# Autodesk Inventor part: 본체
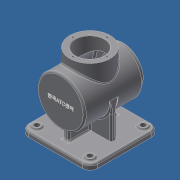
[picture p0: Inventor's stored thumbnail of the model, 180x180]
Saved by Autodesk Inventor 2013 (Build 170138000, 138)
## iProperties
Created: 2015-07
Part Number: 본체
Material: 일반
Document SubType Name: Modeling
Designer: Administrator
Density: 1 g/cm^3
Mass: 471.466 g
Surface Area: 1268.22 cm^2
Volume: 471.466 cm^3
Author: Administrator
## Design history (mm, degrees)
sketch "스케치1"
  geometry: L1 (-65, 65)-(65, 65); L2 (65, 65)-(65, -65); L3 (65, -65)-(-65, -65); L4 (-65, -65)-(-65, 65); 3 further points
  constraints: 8 end point, 2 midpoint, 2 parallel, 1 horizontal, 1 horizontal alignment, 1 perpendicular, 1 vertical alignment
  dimensions: "d0" = 130 distance of L1.start L1.end; "d2" = 130 distance of L1.end L2.end
extrude "돌출1" new body sketch "스케치1" distance "d3" = 10; taper "d4" = 0 deg
node "작업 평면1"
node "작업 평면2"
node "작업 평면3"
sketch "스케치8"
  geometry: L1 (0, 0)-(130, 0) reference; L2 (130, 0)-(130, -10) reference; L3 (0, -10)-(130, -10) reference; L4 (0, 0)-(0, -10) reference; C1 r 45 at (65, 68); 2 further points
  constraints: 1 centre point, 1 midpoint, 1 vertical alignment
  dimensions: "d32" = 90 diameter of C1; "d34" = 78 distance from line of L3 C1.centre
extrude "돌출7" join sketch "스케치8" distance "d35" = 110; taper "d36" = 0 deg
sketch "스케치5"
  geometry: L1 (-45, 5)-(45, 5); L2 (45, 5)-(45, -5); L3 (45, -5)-(-45, -5); L4 (-45, -5)-(-45, 5); L5 (-5, 45)-(5, 45); L6 (5, 45)-(5, -45); L7 (5, -45)-(-5, -45); L8 (-5, -45)-(-5, 45); 5 further points
  constraints: 16 end point, 4 midpoint, 4 parallel, 2 horizontal, 2 horizontal alignment, 2 perpendicular, 2 vertical alignment
  dimensions: "d19" = 10 distance of L1.end L2.end; "d21" = 90 distance of L2.end L3.end; "d27" = 10 distance of L6.end L7.end; "d28" = 90 distance of L7.end L5.start
extrude "돌출6" join sketch "스케치5" stored distance "d29" = 7; taper "d30" = 0 deg
sketch "스케치9"
  geometry: C1 r 45 at (0, 0) reference; C2 r 38 at (0, 0); 1 further point
  constraints: 1 centre point, 1 coincident
  dimensions: "d37" = 76 diameter of C2
extrude "돌출8" join sketch "스케치9" distance "d40" = 7; taper "d41" = 0 deg
node "작업 평면4"
sketch "스케치10"
  geometry: L1 (45, 55)-(-45, 55) reference; L2 (45, -55)-(-45, -55) reference; L3 (45, -5)-(45, 5) reference; L4 (45, -5)-(5, -5) reference; L5 (5, -5)-(5, -45) reference; L6 (5, -45)-(-5, -45) reference; L7 (-5, -45)-(-5, -5) reference; L8 (-5, -5)-(-45, -5) reference; L9 (-45, -5)-(-45, 5) reference; L10 (-45, 5)-(-5, 5) reference; L11 (-5, 5)-(-5, 45) reference; L12 (-5, 45)-(5, 45) reference; L13 (5, 45)-(5, 5) reference; L14 (5, 5)-(45, 5) reference; L15 (45, 5)-(5, 5) reference; L16 (5, 5)-(5, 45) reference; L17 (5, 45)-(-5, 45) reference; L18 (-5, 45)-(-5, 5) reference; L19 (-5, 5)-(-45, 5) reference; L20 (-45, 5)-(-45, -5) reference; L21 (-45, -5)-(-5, -5) reference; L22 (-5, -5)-(-5, -45) reference; L23 (-5, -45)-(5, -45) reference; L24 (5, -45)-(5, -5) reference; L25 (5, -5)-(45, -5) reference; L26 (45, -5)-(45, 5) reference; L27 (65, 65)-(-65, 65) reference; L28 (65, -65)-(65, 65) reference; L29 (-65, -65)-(65, -65) reference; L30 (-65, 65)-(-65, -65) reference; C1 r 38 at (0, 0); 1 further point
  constraints: 1 centre point, 1 coincident
  dimensions: "d43" = 76 diameter of C1
extrude "돌출9" join sketch "스케치10" stored distance "d45" = 7; taper "d46" = 0 deg
sketch "스케치12"
  geometry: L1 (62, 30)-(55, 30) reference; L2 (55, 30)-(55, 23) reference; L3 (55, 23)-(45, 23) reference; L4 (45, 23)-(45, 0) reference; L5 (45, 0)-(65, 0) reference; L6 (65, 0)-(65, -10) reference; L7 (65, -10)-(-65, -10) reference; L8 (-65, -10)-(-65, 0) reference; L9 (-65, 0)-(-45, 0) reference; L10 (-45, 0)-(-45, 23) reference; L11 (-45, 23)-(-55, 23) reference; L12 (-55, 23)-(-55, 113) reference; L13 (-55, 113)-(-38, 113) reference; L14 (-38, 113)-(-38, 130) reference; L15 (-38, 130)-(38, 130) reference; L16 (38, 130)-(38, 113) reference; L17 (38, 113)-(55, 113) reference; L18 (55, 113)-(55, 106) reference; L19 (55, 106)-(62, 106) reference; L20 (62, 106)-(62, 30) reference; L21 (62, 68)-(-55, 68); L22 (62, 95)-(48, 95); L23 (48, 95)-(48, 108); L24 (48, 108)-(-48, 108); L25 (-48, 108)-(-48, 68); 1 further point
  constraints: 10 end point, 2 midpoint, 2 parallel, 2 perpendicular, 2 point on line
  dimensions: "d49" = 80 diameter of L24 L21; "d51" = 14 distance between parallel lines of L20 L23; "d52" = 54 diameter of L22 L21; "d112" = 96 distance between parallel lines of L25 L23
revolve "회전1" sketch "스케치12" stored, may be unused: angle "d54" = 90 deg
hole "구멍1" diameter "d57" = 54; stored, may be unused: countersink angle "d61" = 90 deg, drill point angle "d63" = 118 deg; dims "d55" = 10, "d56" = 10, "d58" = 6, "d59" = 4, "d60" = 2, "d62" = 8
sketch "스케치13"
  geometry: C1 r 27 at (0, 0) reference; C2 r 38 at (0, 0) reference; 2 further points
  constraints: 1 vertical alignment
  dimensions: "d64" = 32 distance of point (0, 32) point (0, 0)
hole "구멍2" sketch "스케치13" at (0, 32) diameter "d65" = 3.242; stored, may be unused: countersink angle "d69" = 90 deg, drill point angle "d71" = 118 deg; dims "d66" = 8, "d67" = 4, "d68" = 2, "d70" = 10
sketch "스케치14"
  geometry: C1 r 27 at (0, 0) reference; C2 r 38 at (0, 0) reference; 2 further points
  constraints: 1 vertical alignment
  dimensions: "d75" = 32 distance of point (0, 32) C1.centre
hole "구멍3" sketch "스케치14" at (0, 32) diameter "d76" = 3.242; stored, may be unused: countersink angle "d80" = 90 deg, drill point angle "d82" = 118 deg; dims "d77" = 8, "d78" = 4, "d79" = 2, "d81" = 10
sketch "스케치15"
  geometry: L1 (-65, 65)-(65, 65) reference; L2 (-65, -65)-(-65, 65) reference; L3 (65, -65)-(-65, -65) reference; L4 (65, 65)-(65, -65) reference; L5 (5, 45)-(5, 5) reference; L6 (5, 5)-(45, 5) reference; L7 (45, 5)-(45, -5) reference; L8 (45, -5)-(5, -5) reference; L9 (5, -5)-(5, -45) reference; L10 (5, -45)-(-5, -45) reference; L11 (-5, -45)-(-5, -5) reference; L12 (-5, -5)-(-45, -5) reference; L13 (-45, -5)-(-45, 5) reference; L14 (-45, 5)-(-5, 5) reference; L15 (-5, 5)-(-5, 45) reference; L16 (-5, 45)-(5, 45) reference; C1 r 7.5 at (-50, -50); C2 r 27 at (0, 0) reference; C3 r 1.621 at (32, 0) reference; C4 r 1.621 at (0, -32) reference; C5 r 1.621 at (-32, 0) reference; C6 r 1.621 at (0, 32) reference; C7 r 27 at (0, 0) reference; C8 r 38 at (0, 0) reference; 1 further point
  constraints: 1 centre point
  dimensions: "d86" = 50 horizontal distance of point (0, 0) C1.centre; "d87" = 15 diameter of C1; "d111" = 50 horizontal distance of point (0, 0) C1.centre
extrude "돌출10" join sketch "스케치15" distance "d88" = 3; taper "d89" = 0 deg
hole "구멍4" diameter "d92" = 10; stored, may be unused: countersink angle "d96" = 90 deg, drill point angle "d98" = 0 deg; dims "d90" = 10, "d91" = 10, "d93" = 8, "d94" = 4, "d95" = 2, "d97" = 10
sketch "스케치16"
  geometry: C1 r 45 at (0, 0) reference; 2 further points
  constraints: 1 coincident, 1 other
feature "엠보싱1" sketch "스케치16" dims "d0" = 130, "d2" = 130, "d19" = 10, "d21" = 90, "d27" = 10, "d28" = 90, "d99" = 0.5, "d100" = 0
chamfer "모따기1" distance "d101" = 1; stored, may be unused: second distance "d102" = 2, angle "d103" = 45 deg
fillet "모깎기1" dims "d104" = 15
fillet "모깎기2" dims "d105" = 3
fillet "모깎기3" dims "d106" = 3
fillet "모깎기4" dims "d107" = 3
fillet "모깎기5" dims "d108" = 3
fillet "모깎기6" dims "d109" = 3
fillet "모깎기7" dims "d110" = 3
node "솔리드1"
pattern_circular "원형 패턴1" dims angle "d73" = 360 deg
pattern_circular "원형 패턴2" dims angle "d84" = 360 deg
mirror "대칭1"
mirror "대칭2"
node "투영된 루프5"
node "투영된 루프6"
node "투영된 루프7"
node "투영된 루프8"
node "투영된 루프10"
node "투영된 루프11"
node "투영된 루프12"
node "투영된 루프13"
node "투영된 루프14"
node "절단 모서리 투영1"
